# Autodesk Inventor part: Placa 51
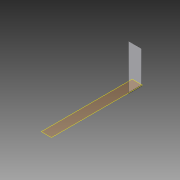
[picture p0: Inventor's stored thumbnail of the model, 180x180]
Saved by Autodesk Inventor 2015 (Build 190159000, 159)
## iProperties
Created: 2015-04
Part Number: Placa 51
Material: Generic
Document SubType Name: Modeling
Designer: suporte
Density: 1 g/cm^3
Appearance: Default
Author: suporte
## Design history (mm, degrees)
workplane "Work Plane1"
sketch "Sketch1"
  geometry: L1 (-47.409, 461.419)-(-47.409, -432.14) reference; L2 (-47.409, -432.14)-(52.591, -432.14) reference; L3 (52.591, -432.14)-(52.591, 361.488) reference; L4 (52.591, 361.488)-(-47.409, 461.419) reference; L5 (-1047.646, 742.86)-(-1047.646, 842.86) reference; L6 (-329.047, 742.86)-(-1047.646, 742.86) reference; L7 (-429.116, 842.86)-(-329.047, 742.86) reference; L8 (-1047.646, 842.86)-(-429.116, 842.86) reference; L9 (52.591, 502.86)-(-281.396, 836.615) reference; L10 (52.591, 361.488)-(52.591, 502.86); L11 (52.591, 502.86)-(-287.646, 842.86); L12 (-287.646, 842.86)-(-429.116, 842.86); L13 (-429.116, 842.86)-(52.591, 361.488); 1 further point
  constraints: 8 end point, 2 collinear, 1 perpendicular, 1 vertical
extrude "Extrusion1" new body sketch "Sketch1" distance "d0" = 12.5; taper "d1" = 0 deg
body "Solid1"
node "Reference1"
node "Reference2"
node "Reference3"
